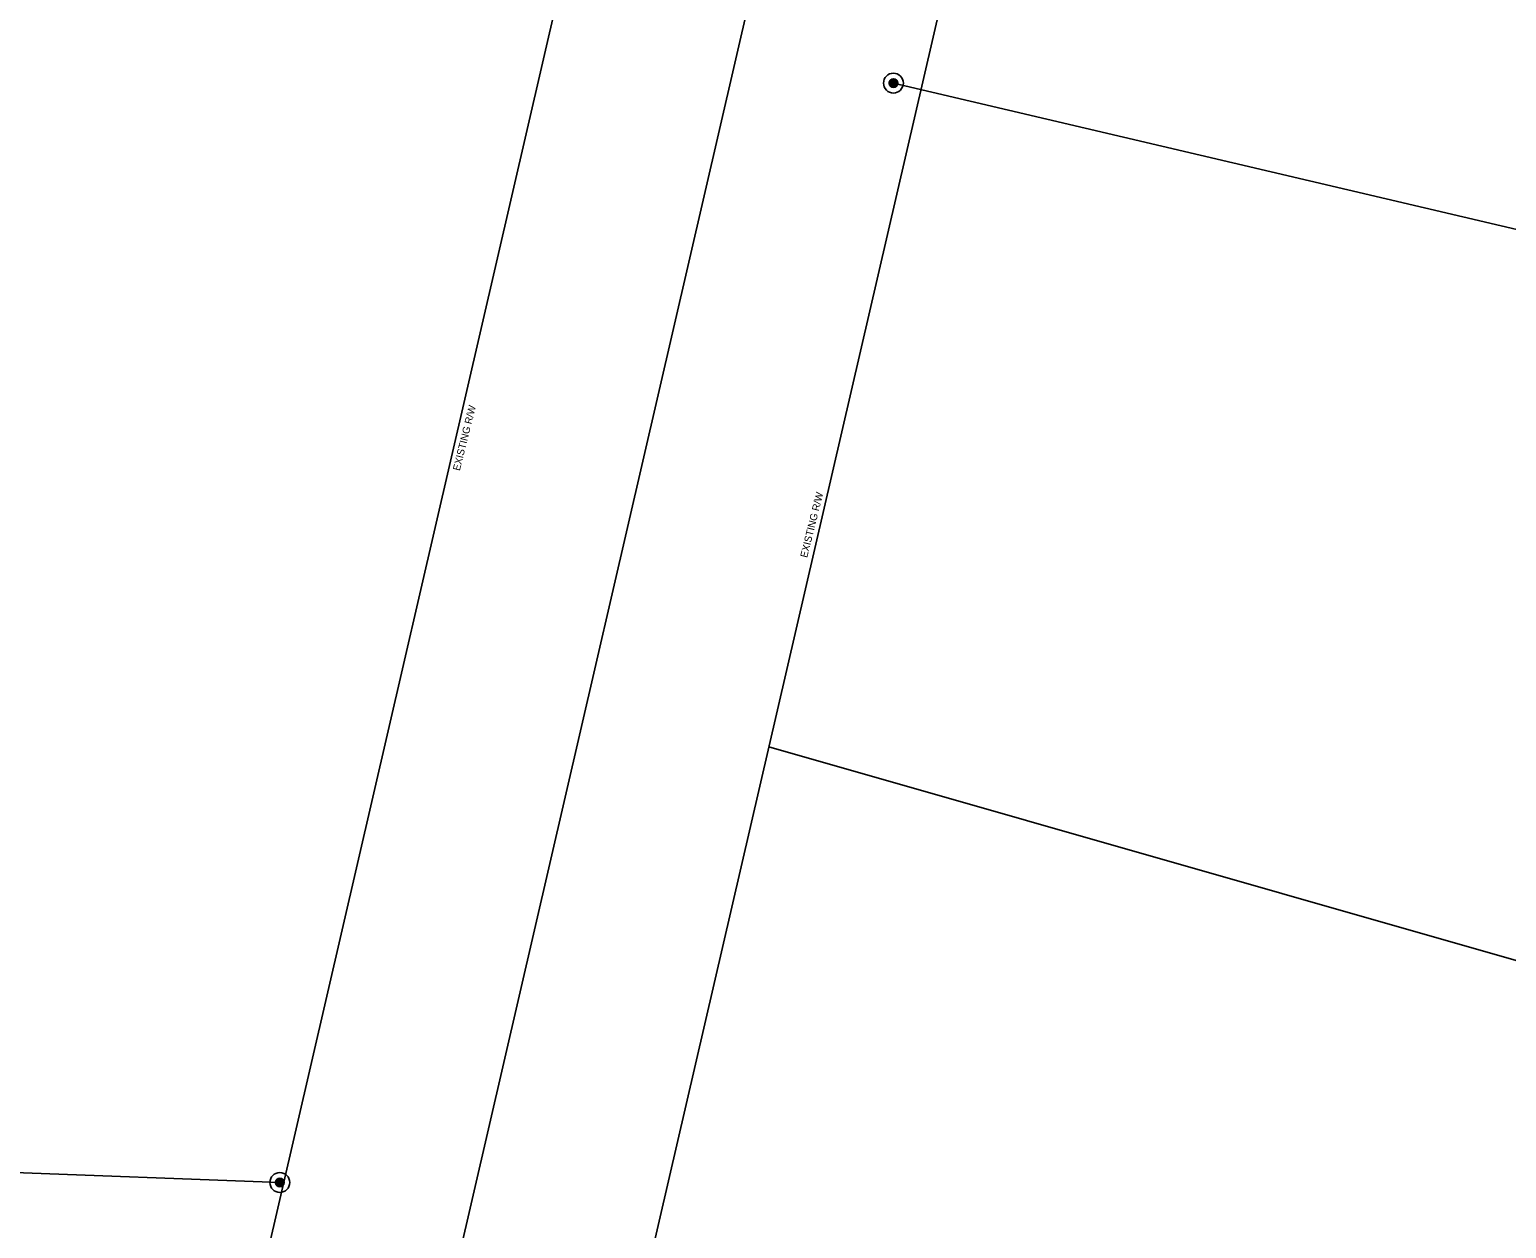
# Model space of a CAD drawing. Extents: x 1398271 to 1401121, y 1018936 to 1022764.
# Drawn here: x 1400405.2 to 1400665.4, y 1021865.9 to 1022077.1 of the extents above; entities that cross this region are included whole.
import ezdxf

# ---------------------------------------------------------------- set-up
doc = ezdxf.new("R2010")
doc.units = 0
for name, color, linetype in [('RD_EX_DV_Prop', 7, 'Continuous'), ('RD_EX_DV_PropPin', 7, 'Continuous'), ('RD_EX_RW', 7, 'Continuous'), ('RD_EX_RW_TX', 7, 'Continuous'), ('RD_HC_Cl', 7, 'Continuous'), ('RD_SMD_Locator', 7, 'Continuous')]:
    doc.layers.add(name, color=color, linetype=linetype)

msp = doc.modelspace()

# ---------------------------------------------------------------- linework, layer by layer
at = {"layer": 'RD_EX_DV_Prop'}
for p, q in [((1400557.36, 1022067.69), (1400710.73, 1022031.63)), ((1400535.42, 1021950.75), (1400818.38, 1021869.84)), ((1400102.72, 1021887.11), (1400449.27, 1021874.03)), ((1400449.27, 1021874.03), (1400449.94, 1021874))]:
    msp.add_line(p, q, dxfattribs=at)
at = {"layer": 'RD_EX_DV_PropPin'}
for p, q in [((1400556.62, 1022067.5), (1400556.62, 1022067.89)), ((1400556.66, 1022067.4), (1400556.66, 1022067.99)), ((1400556.69, 1022067.33), (1400556.69, 1022068.06)), ((1400556.73, 1022067.27), (1400556.73, 1022068.12)), ((1400556.76, 1022067.22), (1400556.76, 1022068.17)), ((1400556.8, 1022067.18), (1400556.8, 1022068.21)), ((1400556.83, 1022067.14), (1400556.83, 1022068.25)), ((1400556.87, 1022067.11), (1400556.87, 1022068.28)), ((1400556.9, 1022067.08), (1400556.9, 1022068.3)), ((1400556.94, 1022067.06), (1400556.94, 1022068.33)), ((1400556.97, 1022067.04), (1400556.97, 1022068.35)), ((1400557.01, 1022067.02), (1400557.01, 1022068.37)), ((1400557.04, 1022067), (1400557.04, 1022068.39)), ((1400557.08, 1022066.99), (1400557.08, 1022068.4)), ((1400557.11, 1022066.97), (1400557.11, 1022068.42)), ((1400557.15, 1022066.96), (1400557.15, 1022068.43)), ((1400557.18, 1022066.95), (1400557.18, 1022068.44)), ((1400557.22, 1022066.95), (1400557.22, 1022068.44)), ((1400557.25, 1022066.94), (1400557.25, 1022068.45)), ((1400557.29, 1022066.94), (1400557.29, 1022068.45)), ((1400557.32, 1022066.93), (1400557.32, 1022068.46)), ((1400557.36, 1022066.93), (1400557.36, 1022068.46)), ((1400557.39, 1022066.93), (1400557.39, 1022068.46)), ((1400557.43, 1022066.94), (1400557.43, 1022068.45)), ((1400557.46, 1022066.94), (1400557.46, 1022068.45)), ((1400557.5, 1022066.95), (1400557.5, 1022068.44)), ((1400557.53, 1022066.95), (1400557.53, 1022068.44)), ((1400557.57, 1022066.96), (1400557.57, 1022068.43)), ((1400557.6, 1022066.97), (1400557.6, 1022068.42)), ((1400557.64, 1022066.99), (1400557.64, 1022068.4)), ((1400557.67, 1022067), (1400557.67, 1022068.39)), ((1400557.71, 1022067.02), (1400557.71, 1022068.37)), ((1400557.74, 1022067.04), (1400557.74, 1022068.35)), ((1400557.78, 1022067.06), (1400557.78, 1022068.33)), ((1400557.81, 1022067.08), (1400557.81, 1022068.3)), ((1400557.85, 1022067.11), (1400557.85, 1022068.28)), ((1400557.88, 1022067.14), (1400557.88, 1022068.25)), ((1400557.92, 1022067.18), (1400557.92, 1022068.21)), ((1400557.95, 1022067.22), (1400557.95, 1022068.17)), ((1400557.99, 1022067.27), (1400557.99, 1022068.12)), ((1400558.02, 1022067.33), (1400558.02, 1022068.06)), ((1400558.06, 1022067.4), (1400558.06, 1022067.99)), ((1400558.09, 1022067.5), (1400558.09, 1022067.89)), ((1400448.53, 1021873.83), (1400448.53, 1021874.22)), ((1400448.57, 1021873.73), (1400448.57, 1021874.32)), ((1400448.6, 1021873.66), (1400448.6, 1021874.39)), ((1400448.64, 1021873.6), (1400448.64, 1021874.45)), ((1400448.67, 1021873.55), (1400448.67, 1021874.5)), ((1400448.71, 1021873.51), (1400448.71, 1021874.54)), ((1400448.74, 1021873.47), (1400448.74, 1021874.58)), ((1400448.78, 1021873.44), (1400448.78, 1021874.61)), ((1400448.81, 1021873.42), (1400448.81, 1021874.64)), ((1400448.85, 1021873.39), (1400448.85, 1021874.66)), ((1400448.88, 1021873.37), (1400448.88, 1021874.68)), ((1400448.92, 1021873.35), (1400448.92, 1021874.7)), ((1400448.95, 1021873.33), (1400448.95, 1021874.72)), ((1400448.99, 1021873.32), (1400448.99, 1021874.73)), ((1400449.02, 1021873.3), (1400449.02, 1021874.75)), ((1400449.06, 1021873.29), (1400449.06, 1021874.76)), ((1400449.09, 1021873.28), (1400449.09, 1021874.77)), ((1400449.13, 1021873.28), (1400449.13, 1021874.77)), ((1400449.16, 1021873.27), (1400449.16, 1021874.78)), ((1400449.2, 1021873.27), (1400449.2, 1021874.78)), ((1400449.23, 1021873.27), (1400449.23, 1021874.79)), ((1400449.27, 1021873.26), (1400449.27, 1021874.79)), ((1400449.3, 1021873.27), (1400449.3, 1021874.79)), ((1400449.34, 1021873.27), (1400449.34, 1021874.78)), ((1400449.37, 1021873.27), (1400449.37, 1021874.78)), ((1400449.41, 1021873.28), (1400449.41, 1021874.77)), ((1400449.44, 1021873.28), (1400449.44, 1021874.77)), ((1400449.48, 1021873.29), (1400449.48, 1021874.76)), ((1400449.51, 1021873.3), (1400449.51, 1021874.75)), ((1400449.55, 1021873.32), (1400449.55, 1021874.73)), ((1400449.58, 1021873.33), (1400449.58, 1021874.72)), ((1400449.62, 1021873.35), (1400449.62, 1021874.7)), ((1400449.65, 1021873.37), (1400449.65, 1021874.68)), ((1400449.69, 1021873.39), (1400449.69, 1021874.66)), ((1400449.72, 1021873.42), (1400449.72, 1021874.64)), ((1400449.76, 1021873.44), (1400449.76, 1021874.61)), ((1400449.79, 1021873.47), (1400449.79, 1021874.58)), ((1400449.83, 1021873.51), (1400449.83, 1021874.54)), ((1400449.86, 1021873.55), (1400449.86, 1021874.5)), ((1400449.9, 1021873.6), (1400449.9, 1021874.45)), ((1400449.93, 1021873.66), (1400449.93, 1021874.39)), ((1400449.97, 1021873.73), (1400449.97, 1021874.32)), ((1400450, 1021873.83), (1400450, 1021874.22))]:
    msp.add_line(p, q, dxfattribs=at)
for centre, radius in [((1400557.36, 1022067.69), 1.75), ((1400557.36, 1022067.69), 0.761), ((1400449.27, 1021874.03), 1.75), ((1400449.27, 1021874.03), 0.761)]:
    msp.add_circle(centre, radius, dxfattribs=at)
at = {"layer": 'RD_EX_RW'}
for p, q in [((1400445.34, 1021854.1), (1400593.32, 1022494.18)), ((1400509.64, 1021839.24), (1400643.96, 1022420.21))]:
    msp.add_line(p, q, dxfattribs=at)
at = {"layer": 'RD_HC_Cl'}
msp.add_line((1400477.49, 1021846.67), (1400606.05, 1022402.73), dxfattribs=at)
at = {"layer": 'RD_SMD_Locator'}
for centre in [(1400557.36, 1022067.69), (1400449.27, 1021874.03)]:
    msp.add_circle(centre, 0.15, dxfattribs=at)

# ---------------------------------------------------------------- texts
at = {"layer": 'RD_EX_RW_TX'}
for p in [(1400480.96, 1021999.31), (1400542.16, 1021984)]:
    msp.add_text('EXISTING R/W', height=1.28, rotation=75.9816, dxfattribs=at).set_placement(p)

doc.saveas('drawing.dxf')
